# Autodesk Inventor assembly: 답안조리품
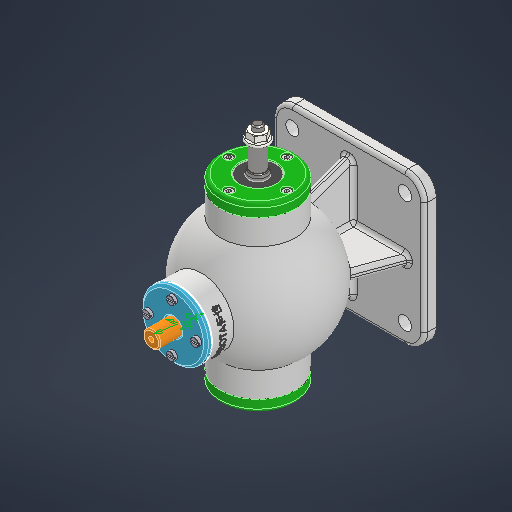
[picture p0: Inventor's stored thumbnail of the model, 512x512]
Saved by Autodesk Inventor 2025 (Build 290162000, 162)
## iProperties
Created: 2025-08
Part Number: 답안조리품
Document SubType Name: Assembly
Designer: infra012
Author: infra012
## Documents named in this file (15)
- C:\Users\infra012\Desktop\750807V1003\답안조립품.iam
- C:\Users\infra012\Desktop\750807V1003\본체.ipt
- C:\Users\infra012\Desktop\750807V1003\V-벨트풀리.ipt
- C:\Users\infra012\Desktop\750807V1003\너트 M8.ipt
- C:\Users\infra012\Desktop\750807V1003\뒤커버.ipt
- C:\Users\infra012\Desktop\750807V1003\베어링- 6202.ipt
- C:\Users\infra012\Desktop\750807V1003\볼트 M4 x 12.ipt
- C:\Users\infra012\Desktop\750807V1003\볼트 M4 x 16.ipt
- C:\Users\infra012\Desktop\750807V1003\상부커버.ipt
- C:\Users\infra012\Desktop\750807V1003\슬라이드.ipt
- C:\Users\infra012\Desktop\750807V1003\앞커버.ipt
- C:\Users\infra012\Desktop\750807V1003\오일실 15 30 7.ipt
- C:\Users\infra012\Desktop\750807V1003\칼라.ipt
- C:\Users\infra012\Desktop\750807V1003\키 4 x 4 x 12.ipt
- C:\Users\infra012\Desktop\750807V1003\편심축.ipt
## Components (1 placed, 1 different names)
1. V-벨트풀리:1
